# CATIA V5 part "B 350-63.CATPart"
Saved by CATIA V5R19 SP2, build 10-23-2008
Part number: BS 350-63
Bounding box of the stored display mesh (mm): x -15.868 to 15.868, y -15.868 to 15.868, z 0 to 177
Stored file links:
  C:\Users\Bora\Desktop\3D Katı model\B serisi\B 350\BS 350-63.CATPart
  C:\Program Files\Dassault Systemes\B19\intel_a\reffiles\standard\MetricThickPitch.txt
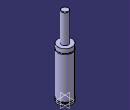
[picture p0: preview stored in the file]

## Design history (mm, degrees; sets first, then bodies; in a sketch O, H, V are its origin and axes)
Body1 (main body)
  Sketch1 on yz-plane, origin (0, 0, 0), H (0, 1, 0), V (0, 0, 1)
    point P3 (8, 176)
    point P5 (8, 176)
    point P7 (16, 102.5)
    point P8 (16, 100.5)
    point P12 (16, 100.5)
    point P13 (16, 102.5)
    line L1 (16, 0) -> (16, 4)
    line L2 (8, 176) -> (8, 112)
    arc A1 centre (7, 176) radius 1 from (8, 176) to (7, 177) ccw
    arc A2 centre (16, 101.5) radius 1 from (16, 102.5) to (16, 100.5) ccw
    line L3 (13.5, 7.5) -> (13.5, 4)
    line L4 (16, 7.5) -> (16, 100.5)
    line L5 (16, 102.5) -> (16, 112)
    line L6 (7, 177) -> (0, 177)
    point P15 (0, 177)
    line L7 (8, 112) -> (16, 112)
    line L8 (0, 0) -> (16, 0)
    line L9 (13.5, 7.5) -> (16, 7.5)
    line L10 (13.5, 4) -> (16, 4)
    coincidence: P15 V, P3 P5, P7 P13, P8 P12
    tangency: L6 A1
    horizontal: L7 H, L8 H, L9 H, L10 H
  Shaft1: profile Sketch1, axis Sketch1.V, angle 360
  Sketch2 on face of Shaft1 from Sketch1.L8, origin (0, 0, 0), H (1, 0, 0), V (0, -1, 0)
    point P1 (0, 0)
  Hole1: placed by Sketch2, at (0, 0, 0) direction (0, 0, 1), diameter 6.647, depth 7, threaded "M8", thread diameter 8, thread depth 7, pitch 1.25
